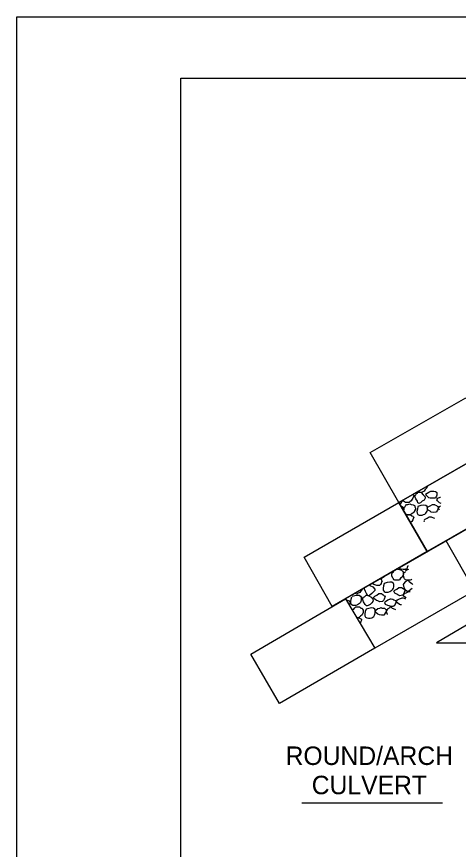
# Model space of a CAD drawing. Extents: x 593 to 1473, y 721 to 1315.
# Drawn here: x 592.7 to 700.2, y 1112.5 to 1315.4 of the extents above; entities that cross this region are included whole.
import ezdxf

# ---------------------------------------------------------------- set-up
doc = ezdxf.new("R2010")
doc.units = 0
doc.layers.add('2', color=7, linetype='Continuous')
doc.layers.add('PLT-BNDY', color=7, linetype='Continuous')

msp = doc.modelspace()

# ---------------------------------------------------------------- linework, layer by layer
at = {"layer": '2'}
for p, q in [((632.66, 736.4), (632.66, 1300.4)), ((632.66, 1300.4), (1418.66, 1300.4)), ((730.91, 1207.04), (672.78, 1173.54)), ((734.66, 1193.04), (679.91, 1161.54)), ((704.16, 1175.54), (697.28, 1187.66)), ((725.16, 1180.66), (694.91, 1162.79)), ((672.78, 1173.54), (679.91, 1161.54)), ((694.91, 1162.79), (707.66, 1162.79)), ((662.16, 1123.79), (696.41, 1123.79))]:
    msp.add_line(p, q, dxfattribs=at)
for points in [[(685.78, 1197.04), (678.78, 1209.16), (702.03, 1222.54), (709.03, 1210.41)], [(709.03, 1210.41), (715.91, 1198.41), (692.66, 1185.04), (685.78, 1197.04)], [(669.53, 1171.66), (662.66, 1183.66), (685.78, 1197.04), (692.66, 1185.04)], [(672.78, 1173.54), (679.91, 1161.54), (656.66, 1148.04), (649.66, 1160.04)]]:
    msp.add_lwpolyline(points, close=True, dxfattribs=at)
for points in [[(690.28, 1199.29), (690.41, 1199.54)], [(690.41, 1199.54), (690.66, 1199.54)], [(690.66, 1199.79), (690.53, 1199.79)], [(690.78, 1199.54), (690.66, 1199.79)], [(690.66, 1199.54), (690.66, 1199.54)], [(690.66, 1199.54), (691.16, 1199.41)], [(691.03, 1199.41), (690.78, 1199.54)], [(691.16, 1199.41), (691.03, 1199.41)], [(691.41, 1199.54), (691.16, 1199.41)], [(691.16, 1199.41), (691.66, 1198.91)], [(691.91, 1199.79), (691.41, 1199.54)], [(692.16, 1200.16), (691.91, 1199.79)], [(692.53, 1200.54), (692.16, 1200.16)], [(692.66, 1200.79), (692.53, 1200.54)], [(692.66, 1199.29), (693.03, 1199.54)], [(693.03, 1199.54), (693.53, 1199.79)], [(693.53, 1199.79), (693.66, 1199.79)], [(693.66, 1199.79), (694.03, 1199.79)], [(694.03, 1199.79), (694.28, 1199.79)], [(694.28, 1199.79), (694.66, 1199.66)], [(694.66, 1199.66), (694.91, 1199.54)], [(694.91, 1199.54), (695.03, 1199.41)], [(695.03, 1199.41), (695.03, 1199.16)], [(686.53, 1197.41), (686.41, 1197.16)], [(686.53, 1197.54), (686.53, 1197.41)], [(686.91, 1197.29), (686.66, 1197.54)], [(686.66, 1197.54), (686.66, 1197.54)], [(687.41, 1197.04), (686.91, 1197.29)], [(686.91, 1197.29), (686.91, 1197.29)], [(688.78, 1197.41), (688.41, 1197.16)], [(689.03, 1197.79), (688.78, 1197.41)], [(689.16, 1198.04), (689.03, 1197.79)], [(689.16, 1199.04), (689.28, 1198.91)], [(689.28, 1198.29), (689.16, 1198.04)], [(689.28, 1198.91), (689.41, 1198.79)], [(689.41, 1198.54), (689.28, 1198.29)], [(689.41, 1198.79), (689.41, 1198.54)], [(689.66, 1198.66), (689.91, 1198.91)], [(689.91, 1197.91), (689.66, 1198.54)], [(689.91, 1198.91), (690.03, 1199.16)], [(690.28, 1197.29), (689.91, 1197.91)], [(690.03, 1199.16), (690.28, 1199.29)], [(690.41, 1196.91), (690.28, 1197.29)], [(691.41, 1197.29), (691.03, 1196.91)], [(691.91, 1197.54), (691.41, 1197.29)], [(691.66, 1198.91), (692.16, 1198.41)], [(692.16, 1198.04), (691.91, 1197.54)], [(692.16, 1198.41), (692.16, 1198.29)], [(692.16, 1198.29), (692.16, 1198.04)], [(692.28, 1199.04), (692.66, 1199.29)], [(692.41, 1198.79), (692.28, 1198.91)], [(692.66, 1198.54), (692.41, 1198.79)], [(693.03, 1198.16), (692.66, 1198.54)], [(693.41, 1198.04), (693.03, 1198.16)], [(693.91, 1198.04), (693.41, 1198.04)], [(694.41, 1198.04), (693.91, 1198.04)], [(694.53, 1198.04), (694.41, 1198.04)], [(694.66, 1198.16), (694.53, 1198.04)], [(694.91, 1198.54), (694.66, 1198.16)], [(695.03, 1198.79), (694.91, 1198.54)], [(695.03, 1199.16), (695.03, 1198.79)], [(695.03, 1197.66), (695.28, 1198.04)], [(695.16, 1197.41), (695.03, 1197.66)], [(695.28, 1197.29), (695.16, 1197.41)], [(695.28, 1198.04), (695.78, 1198.29)], [(695.66, 1196.91), (695.28, 1197.29)], [(695.78, 1198.29), (695.91, 1198.29)], [(686.16, 1196.79), (686.03, 1196.66)], [(686.41, 1197.16), (686.16, 1196.79)], [(686.28, 1196.04), (686.53, 1196.04)], [(686.53, 1196.04), (686.91, 1195.54)], [(686.91, 1195.41), (687.03, 1195.79)], [(686.91, 1195.54), (687.03, 1195.29)], [(686.91, 1195.04), (686.91, 1195.41)], [(687.03, 1195.29), (686.91, 1195.16)], [(687.03, 1195.79), (687.28, 1196.04)], [(687.03, 1195.79), (687.03, 1195.79)], [(687.28, 1196.04), (687.41, 1196.04)], [(687.66, 1197.04), (687.41, 1197.04)], [(687.41, 1196.16), (687.53, 1196.41)], [(687.53, 1196.41), (687.66, 1196.54)], [(687.91, 1197.04), (687.66, 1197.04)], [(687.66, 1196.54), (687.91, 1196.54)], [(688.28, 1197.04), (687.91, 1197.04)], [(687.91, 1196.54), (688.41, 1196.66)], [(688.41, 1197.16), (688.28, 1197.04)], [(688.41, 1196.66), (688.78, 1196.54)], [(688.78, 1196.54), (689.28, 1196.41)], [(689.28, 1196.41), (689.53, 1196.29)], [(689.53, 1196.29), (689.66, 1196.16)], [(689.66, 1196.16), (689.66, 1195.91)], [(689.66, 1195.91), (689.78, 1195.66)], [(689.78, 1195.41), (689.66, 1195.16)], [(689.78, 1195.66), (689.78, 1195.41)], [(690.66, 1196.79), (690.41, 1196.91)], [(691.03, 1196.91), (690.66, 1196.79)], [(690.66, 1196.79), (690.66, 1196.79)], [(692.66, 1195.66), (692.91, 1195.91)], [(692.78, 1195.29), (692.66, 1195.54)], [(692.91, 1195.16), (692.78, 1195.29)], [(692.91, 1195.91), (693.41, 1196.16)], [(693.41, 1196.16), (693.91, 1196.54)], [(693.91, 1196.54), (694.16, 1196.54)], [(694.16, 1196.54), (694.41, 1196.54)], [(694.41, 1196.54), (694.53, 1196.41)], [(694.53, 1196.41), (694.91, 1196.29)], [(694.91, 1196.29), (695.16, 1196.04)], [(695.16, 1196.04), (695.28, 1196.04)], [(695.28, 1195.41), (695.16, 1195.16)], [(695.28, 1196.04), (695.41, 1195.79)], [(695.41, 1195.79), (695.28, 1195.41)], [(695.66, 1195.16), (695.41, 1195.66)], [(695.53, 1195.79), (695.66, 1196.04)], [(696.03, 1196.79), (695.66, 1196.91)], [(695.66, 1196.04), (695.91, 1196.16)], [(688.16, 1193.91), (687.66, 1194.04)], [(687.66, 1194.04), (687.66, 1194.04)], [(687.66, 1193.91), (687.91, 1194.04)], [(687.91, 1194.04), (688.03, 1194.04)], [(688.03, 1194.04), (688.41, 1194.04)], [(688.28, 1193.91), (688.16, 1193.91)], [(688.66, 1194.04), (688.28, 1193.91)], [(688.41, 1194.04), (688.53, 1194.04)], [(688.53, 1194.04), (688.91, 1193.79)], [(688.78, 1194.16), (688.66, 1194.04)], [(689.16, 1194.41), (688.78, 1194.16)], [(688.91, 1193.79), (689.16, 1193.66)], [(689.41, 1194.66), (689.16, 1194.41)], [(689.16, 1193.66), (689.28, 1193.54)], [(689.28, 1193.54), (689.41, 1193.41)], [(689.41, 1193.41), (689.28, 1193.04)], [(689.66, 1195.04), (689.41, 1194.66)], [(689.66, 1195.16), (689.66, 1195.04)], [(692.66, 1193.16), (693.16, 1193.54)], [(693.41, 1194.91), (692.91, 1195.16)], [(693.16, 1193.54), (693.28, 1193.54)], [(693.28, 1193.54), (693.66, 1193.54)], [(693.66, 1194.66), (693.41, 1194.91)], [(694.16, 1194.54), (693.66, 1194.66)], [(693.66, 1193.54), (693.78, 1193.41)], [(693.78, 1193.41), (694.16, 1193.29)], [(694.78, 1194.66), (694.16, 1194.54)], [(694.16, 1193.29), (694.41, 1193.16)], [(694.91, 1194.66), (694.78, 1194.66)], [(695.03, 1194.91), (694.91, 1194.66)], [(695.16, 1195.16), (695.03, 1194.91)], [(688.91, 1192.29), (688.78, 1192.29)], [(689.16, 1192.79), (688.91, 1192.41)], [(688.91, 1192.41), (688.91, 1192.29)], [(689.28, 1193.04), (689.16, 1192.79)], [(691.91, 1192.66), (692.16, 1192.91)], [(692.03, 1192.29), (691.91, 1192.54)], [(692.03, 1192.29), (692.03, 1192.29)], [(692.16, 1192.91), (692.66, 1193.16)], [(685.91, 1180.91), (685.91, 1181.04)], [(687.78, 1181.16), (687.66, 1180.79)], [(687.91, 1181.54), (687.78, 1181.16)], [(687.91, 1181.66), (687.91, 1181.54)], [(684.03, 1179.54), (684.16, 1179.79)], [(684.03, 1179.16), (684.03, 1179.54)], [(684.28, 1178.54), (684.03, 1179.16)], [(684.16, 1179.79), (684.16, 1180.04)], [(684.16, 1180.04), (684.41, 1180.04)], [(684.41, 1180.16), (684.53, 1180.16)], [(684.53, 1180.29), (684.53, 1180.29)], [(685.41, 1180.79), (685.41, 1180.79)], [(685.41, 1180.79), (685.91, 1180.66)], [(686.28, 1180.79), (685.91, 1180.91)], [(685.91, 1180.66), (686.41, 1180.54)], [(686.78, 1180.66), (686.28, 1180.79)], [(686.41, 1180.54), (686.66, 1180.29)], [(686.66, 1179.04), (686.53, 1178.79)], [(686.66, 1180.29), (686.66, 1180.29)], [(686.66, 1180.29), (686.78, 1180.04)], [(686.78, 1179.29), (686.66, 1179.04)], [(687.41, 1180.66), (686.78, 1180.66)], [(686.78, 1180.04), (686.91, 1179.66)], [(686.91, 1179.54), (686.78, 1179.29)], [(686.91, 1179.79), (687.03, 1179.91)], [(686.91, 1179.54), (686.91, 1179.79)], [(686.91, 1179.66), (686.91, 1179.54)], [(686.91, 1179.16), (686.91, 1179.54)], [(687.03, 1178.54), (686.91, 1179.16)], [(687.03, 1179.91), (687.28, 1180.04)], [(687.28, 1180.04), (687.41, 1180.16)], [(687.66, 1180.79), (687.41, 1180.79)], [(687.41, 1180.79), (687.41, 1180.66)], [(687.41, 1180.29), (687.53, 1180.41)], [(687.53, 1180.41), (687.66, 1180.66)], [(687.66, 1180.66), (687.91, 1180.66)], [(687.91, 1180.66), (688.16, 1180.79)], [(679.66, 1177.04), (679.28, 1177.29)], [(679.91, 1176.91), (679.66, 1177.04)], [(681.28, 1177.04), (681.03, 1176.79)], [(681.28, 1178.41), (681.41, 1178.29)], [(681.41, 1177.29), (681.28, 1177.04)], [(681.66, 1178.54), (681.41, 1178.41)], [(681.41, 1178.41), (681.41, 1178.41)], [(681.41, 1178.29), (681.53, 1178.04)], [(681.53, 1177.66), (681.41, 1177.29)], [(681.53, 1178.04), (681.66, 1177.91)], [(681.66, 1177.91), (681.53, 1177.66)], [(682.03, 1178.79), (681.66, 1178.54)], [(682.16, 1178.79), (682.03, 1178.79)], [(682.16, 1178.79), (682.16, 1178.79)], [(684.41, 1178.41), (684.28, 1178.54)], [(684.53, 1178.16), (684.41, 1178.41)], [(684.78, 1178.04), (684.53, 1178.16)], [(685.16, 1178.04), (684.78, 1178.04)], [(685.41, 1178.04), (685.16, 1178.04)], [(685.78, 1178.04), (685.41, 1178.04)], [(685.91, 1178.16), (685.78, 1178.04)], [(686.16, 1178.54), (685.91, 1178.16)], [(686.53, 1178.79), (686.16, 1178.54)], [(686.91, 1177.04), (687.03, 1177.29)], [(687.03, 1176.29), (686.91, 1177.04)], [(687.16, 1178.41), (687.03, 1178.54)], [(687.03, 1177.29), (687.41, 1177.66)], [(687.41, 1178.16), (687.16, 1178.41)], [(687.66, 1178.04), (687.41, 1178.16)], [(687.41, 1177.79), (687.66, 1177.91)], [(687.41, 1177.66), (687.41, 1177.79)], [(688.03, 1178.04), (687.66, 1178.04)], [(687.66, 1177.91), (687.78, 1178.04)], [(687.78, 1178.04), (687.91, 1178.04)], [(687.91, 1178.04), (688.28, 1177.79)], [(688.28, 1178.04), (688.03, 1178.04)], [(688.53, 1178.04), (688.28, 1178.04)], [(688.28, 1177.79), (688.91, 1177.29)], [(688.78, 1178.16), (688.53, 1178.04)], [(688.91, 1178.29), (688.78, 1178.16)], [(688.91, 1177.29), (689.16, 1177.04)], [(676.28, 1175.04), (675.66, 1174.79)], [(676.53, 1175.41), (676.28, 1175.04)], [(676.91, 1175.79), (676.53, 1175.41)], [(676.91, 1175.79), (676.91, 1175.79)], [(677.28, 1176.04), (677.41, 1176.16)], [(677.66, 1175.29), (677.28, 1176.04)], [(677.91, 1174.79), (677.66, 1175.29)], [(678.66, 1176.91), (678.66, 1176.79)], [(678.66, 1176.79), (679.41, 1176.41)], [(679.41, 1175.04), (679.16, 1174.79)], [(679.41, 1176.41), (679.91, 1175.91)], [(679.91, 1175.54), (679.41, 1175.04)], [(680.41, 1176.79), (679.91, 1176.91)], [(679.91, 1175.91), (679.91, 1175.66)], [(679.91, 1175.66), (679.91, 1175.54)], [(680.91, 1176.79), (680.41, 1176.79)], [(681.03, 1176.79), (680.91, 1176.79)], [(684.53, 1175.41), (684.78, 1175.66)], [(684.66, 1175.04), (684.53, 1175.41)], [(684.78, 1174.91), (684.66, 1175.04)], [(684.78, 1175.66), (685.28, 1175.91)], [(685.28, 1175.91), (685.78, 1176.29)], [(685.78, 1176.29), (685.91, 1176.29)], [(685.91, 1176.29), (686.16, 1176.29)], [(686.16, 1176.29), (686.41, 1176.29)], [(686.41, 1176.29), (686.78, 1176.04)], [(686.78, 1176.04), (687.03, 1175.79)], [(687.03, 1175.04), (686.91, 1174.66)], [(687.41, 1175.66), (687.03, 1176.29)], [(687.03, 1175.79), (687.16, 1175.79)], [(687.16, 1175.29), (687.03, 1175.04)], [(687.16, 1175.79), (687.28, 1175.54)], [(687.28, 1175.54), (687.16, 1175.29)], [(687.16, 1174.79), (687.66, 1175.04)], [(687.66, 1175.41), (687.41, 1175.66)], [(687.78, 1175.29), (687.66, 1175.41)], [(687.66, 1175.04), (688.16, 1175.29)], [(688.03, 1175.29), (687.78, 1175.29)], [(688.16, 1175.41), (688.03, 1175.29)], [(688.66, 1175.79), (688.16, 1175.41)], [(688.16, 1175.29), (688.28, 1175.29)], [(688.28, 1175.29), (688.53, 1175.29)], [(689.03, 1176.04), (688.66, 1175.79)], [(673.03, 1173.29), (673.03, 1173.29)], [(673.03, 1173.29), (673.41, 1173.16)], [(673.41, 1173.16), (673.66, 1173.04)], [(673.66, 1173.04), (673.78, 1172.79)], [(675.28, 1174.79), (675.16, 1174.79)], [(675.41, 1174.66), (675.28, 1174.79)], [(675.53, 1174.66), (675.41, 1174.66)], [(675.66, 1174.79), (675.53, 1174.66)], [(676.91, 1173.54), (677.16, 1173.91)], [(677.16, 1172.79), (676.91, 1173.54)], [(677.16, 1173.91), (677.41, 1174.04)], [(677.41, 1174.04), (677.66, 1174.29)], [(677.66, 1174.29), (677.78, 1174.41)], [(677.78, 1174.41), (677.91, 1174.41)], [(678.16, 1174.29), (677.91, 1174.79)], [(677.91, 1174.41), (677.91, 1174.41)], [(677.91, 1174.41), (678.41, 1174.29)], [(678.28, 1174.29), (678.16, 1174.29)], [(678.41, 1174.29), (678.28, 1174.29)], [(678.66, 1174.41), (678.41, 1174.29)], [(678.41, 1174.29), (679.03, 1173.91)], [(679.16, 1174.79), (678.66, 1174.41)], [(679.03, 1173.91), (679.41, 1173.41)], [(679.41, 1173.41), (679.53, 1173.29)], [(679.53, 1173.29), (679.41, 1172.91)], [(679.66, 1173.91), (679.91, 1174.16)], [(679.78, 1173.54), (679.66, 1173.91)], [(679.91, 1173.41), (679.78, 1173.54)], [(679.91, 1174.16), (680.41, 1174.41)], [(680.28, 1173.16), (679.91, 1173.41)], [(680.66, 1173.04), (680.28, 1173.16)], [(680.41, 1174.41), (680.91, 1174.79)], [(681.16, 1172.79), (680.66, 1173.04)], [(680.91, 1174.79), (680.91, 1174.79)], [(680.91, 1174.79), (681.41, 1174.79)], [(681.41, 1174.79), (681.53, 1174.79)], [(681.53, 1174.79), (681.91, 1174.54)], [(682.03, 1173.16), (681.78, 1172.91)], [(681.91, 1174.54), (682.16, 1174.29)], [(682.16, 1173.41), (682.03, 1173.16)], [(682.16, 1174.29), (682.28, 1174.29)], [(682.28, 1173.66), (682.16, 1173.41)], [(682.28, 1174.29), (682.41, 1174.04)], [(682.41, 1174.04), (682.28, 1173.66)], [(682.53, 1172.91), (683.03, 1173.29)], [(683.03, 1173.29), (683.53, 1173.41)], [(683.53, 1173.41), (683.66, 1173.54)], [(683.66, 1173.54), (683.91, 1173.54)], [(683.91, 1173.54), (684.28, 1173.41)], [(684.28, 1173.41), (684.53, 1173.29)], [(684.53, 1173.29), (684.91, 1173.16)], [(685.28, 1174.66), (684.78, 1174.91)], [(684.91, 1173.16), (685.03, 1173.04)], [(685.03, 1173.04), (685.03, 1172.79)], [(685.16, 1172.91), (685.41, 1173.29)], [(685.53, 1174.54), (685.28, 1174.66)], [(685.41, 1173.29), (685.91, 1173.54)], [(686.03, 1174.29), (685.53, 1174.54)], [(685.91, 1173.54), (686.41, 1173.66)], [(686.66, 1174.41), (686.03, 1174.29)], [(686.41, 1173.66), (686.53, 1173.79)], [(686.53, 1173.79), (686.78, 1173.79)], [(686.91, 1174.66), (686.66, 1174.41)], [(686.66, 1174.41), (686.66, 1174.41)], [(686.78, 1173.79), (687.03, 1173.66)], [(686.91, 1174.41), (687.16, 1174.79)], [(686.91, 1174.16), (686.91, 1174.41)], [(687.16, 1174.04), (686.91, 1174.16)], [(687.03, 1173.66), (687.41, 1173.54)], [(687.53, 1173.79), (687.16, 1174.04)], [(687.41, 1173.54), (687.41, 1173.54)], [(673.78, 1172.41), (673.66, 1172.16)], [(673.78, 1172.79), (673.91, 1172.66)], [(673.91, 1172.66), (673.78, 1172.41)], [(674.53, 1170.91), (674.53, 1171.04)], [(674.53, 1171.04), (674.78, 1171.04)], [(674.78, 1171.04), (674.91, 1171.29)], [(674.91, 1171.29), (675.03, 1171.41)], [(675.03, 1171.41), (675.28, 1171.54)], [(675.28, 1171.54), (675.66, 1171.54)], [(675.66, 1171.54), (676.16, 1171.54)], [(676.16, 1171.54), (676.53, 1171.29)], [(676.53, 1171.29), (676.78, 1171.29)], [(676.78, 1171.29), (676.91, 1171.04)], [(676.91, 1171.04), (677.03, 1170.79)], [(677.53, 1172.16), (677.16, 1172.79)], [(677.78, 1171.91), (677.53, 1172.16)], [(677.91, 1171.79), (677.78, 1171.91)], [(678.03, 1171.79), (677.91, 1171.79)], [(678.28, 1171.91), (678.03, 1171.79)], [(678.78, 1172.16), (678.28, 1171.91)], [(679.16, 1172.54), (678.78, 1172.16)], [(679.41, 1172.91), (679.16, 1172.54)], [(680.16, 1170.79), (680.66, 1171.16)], [(680.66, 1171.16), (681.16, 1171.29)], [(681.66, 1172.91), (681.16, 1172.79)], [(681.16, 1171.29), (681.41, 1171.41)], [(681.41, 1171.41), (681.66, 1171.29)], [(681.78, 1172.91), (681.66, 1172.91)], [(681.66, 1171.29), (681.91, 1171.29)], [(681.91, 1171.29), (682.28, 1171.29)], [(682.28, 1172.66), (682.53, 1172.91)], [(682.41, 1172.41), (682.28, 1172.54)], [(682.28, 1171.29), (682.53, 1171.04)], [(682.53, 1172.16), (682.41, 1172.41)], [(683.03, 1171.91), (682.53, 1172.16)], [(682.53, 1171.04), (682.66, 1170.91)], [(682.66, 1170.91), (682.66, 1170.79)], [(682.78, 1170.54), (683.03, 1171.04)], [(683.41, 1171.79), (683.03, 1171.91)], [(683.03, 1171.04), (683.16, 1171.16)], [(683.16, 1171.16), (683.28, 1171.29)], [(683.28, 1171.29), (683.66, 1171.41)], [(683.91, 1171.66), (683.41, 1171.79)], [(683.66, 1171.41), (683.66, 1171.54)], [(683.66, 1171.54), (683.78, 1171.54)], [(683.78, 1171.54), (684.16, 1171.29)], [(684.41, 1171.66), (683.91, 1171.66)], [(684.16, 1171.29), (684.78, 1171.04)], [(684.53, 1171.79), (684.41, 1171.66)], [(684.66, 1171.79), (684.53, 1171.79)], [(684.78, 1172.16), (684.66, 1171.79)], [(685.03, 1172.54), (684.78, 1172.16)], [(684.78, 1171.04), (684.91, 1170.91)], [(685.03, 1172.79), (685.03, 1172.54)], [(685.28, 1172.66), (685.16, 1172.79)], [(685.41, 1172.54), (685.28, 1172.66)], [(685.91, 1172.16), (685.41, 1172.54)], [(686.16, 1172.04), (685.91, 1172.16)], [(686.41, 1172.04), (686.16, 1172.04)], [(675.91, 1168.91), (675.66, 1168.91)], [(675.66, 1168.91), (675.91, 1168.91)], [(676.16, 1169.04), (675.91, 1168.91)], [(675.91, 1168.91), (676.16, 1168.79)], [(676.41, 1169.29), (676.16, 1169.04)], [(676.78, 1169.66), (676.41, 1169.29)], [(676.91, 1169.79), (676.78, 1169.66)], [(677.03, 1170.16), (676.91, 1169.79)], [(677.03, 1170.79), (677.03, 1170.54)], [(677.03, 1170.54), (677.03, 1170.41)], [(677.03, 1170.41), (677.03, 1170.16)], [(679.91, 1170.54), (680.16, 1170.79)], [(680.03, 1170.29), (679.91, 1170.54)], [(680.16, 1170.16), (680.03, 1170.29)], [(680.66, 1169.79), (680.16, 1170.16)], [(681.03, 1169.66), (680.66, 1169.79)], [(681.53, 1169.54), (681.03, 1169.66)], [(682.16, 1169.54), (681.53, 1169.54)], [(682.28, 1169.79), (682.16, 1169.66)], [(682.16, 1169.66), (682.16, 1169.54)], [(682.53, 1170.16), (682.28, 1169.79)], [(682.66, 1170.41), (682.53, 1170.16)], [(682.66, 1170.79), (682.66, 1170.41)], [(682.91, 1169.79), (682.78, 1170.54)], [(683.03, 1169.79), (682.91, 1169.79)], [(676.16, 1168.79), (676.53, 1168.66)], [(676.53, 1168.04), (676.41, 1167.66)], [(676.41, 1167.66), (676.41, 1167.66)], [(676.53, 1168.66), (676.66, 1168.54)], [(676.66, 1168.29), (676.53, 1168.04)], [(676.66, 1168.54), (676.66, 1168.29)]]:
    msp.add_lwpolyline(points, dxfattribs=at)
for points in [[(690.41, 1196.04), (692.66, 1196.04), (692.66, 1194.91), (691.78, 1194.04), (690.41, 1194.04), (690.41, 1196.04)], [(682.16, 1177.29), (684.41, 1177.29), (684.41, 1176.16), (683.53, 1175.29), (682.16, 1175.29), (682.16, 1177.29)], [(674.41, 1174.16), (676.41, 1174.16), (676.53, 1172.91), (675.66, 1172.04), (674.28, 1172.04), (674.28, 1174.04)], [(677.78, 1171.04), (679.91, 1171.04), (679.91, 1169.79), (679.16, 1168.91), (677.66, 1169.04), (677.78, 1171.04)]]:
    msp.add_spline(points, degree=3, dxfattribs=at)
at = {"layer": 'PLT-BNDY'}
msp.add_lwpolyline([(592.66, 1315.4), (1433.66, 1315.4), (1433.66, 721.4), (592.66, 721.4)], close=True, dxfattribs=at)

# ---------------------------------------------------------------- texts
at = {"layer": '2'}
for s, p in [('ROUND/ARCH', (658.16, 1133.04)), ('CULVERT', (664.53, 1125.91))]:
    msp.add_text(s, height=4.5, dxfattribs=at).set_placement(p)

doc.saveas('drawing.dxf')
